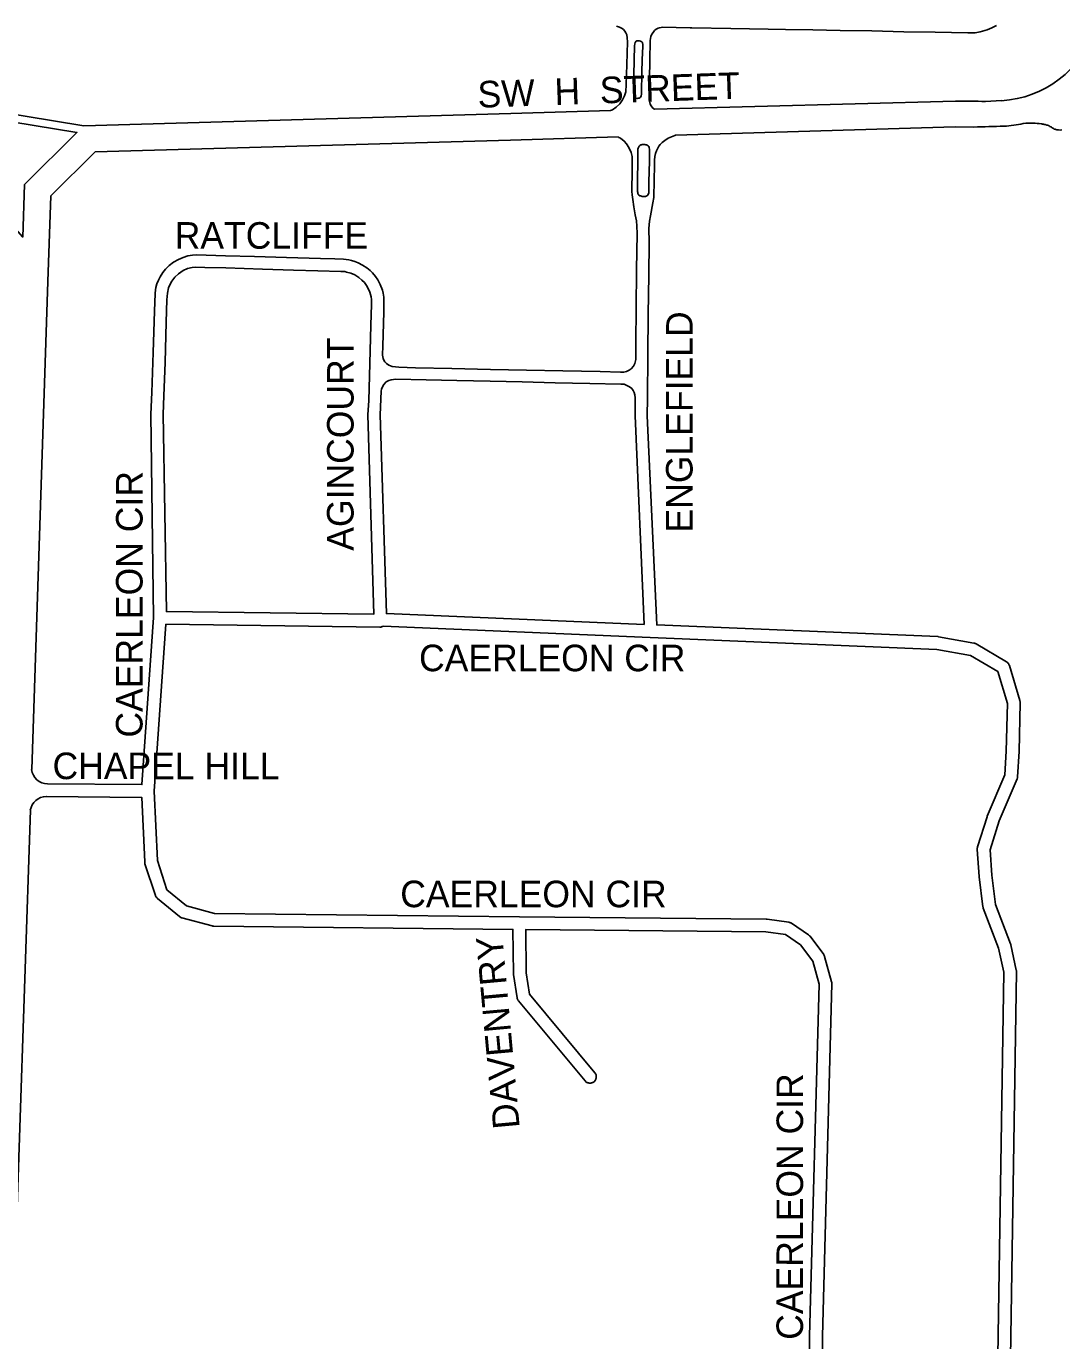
# Model space of a CAD drawing. Extents: x 0 to 712119, y 0 to 761125.
# Drawn here: x 656157 to 658107, y 728628 to 731101 of the extents above; entities that cross this region are included whole.
import ezdxf

# ---------------------------------------------------------------- set-up
doc = ezdxf.new("R2010")
doc.units = 0
doc.layers.add('PAVED ROADS', color=7, linetype='Continuous')
doc.layers.add('street names', color=7, linetype='Continuous')

msp = doc.modelspace()

# ---------------------------------------------------------------- linework, layer by layer
at = {"layer": 'PAVED ROADS'}
for points in [[(657267.9, 731101.4), (657274, 731099.7), (657278.9, 731097.1), (657281.3, 731095), (657283.8, 731092.2), (657286, 731088.9), (657287.5, 731085), (657288.5, 731079.4), (657288.9, 731071.9), (657287.5, 731029.4), (657286.7, 730992), (657285.5, 730977.9), (657283.5, 730970.5), (657279.6, 730963), (657274.2, 730955.5), (657267.3, 730949), (657260.5, 730944.3), (657257, 730942.5), (657069, 730937.3), (656265.2, 730914.2), (655883.9, 730976.8), (655357.5, 731004.3), (653623.9, 731094.8), (653552.8, 731124.8)], [(657906.8, 730960.6), (657339.5, 730945), (657336.8, 730947.1), (657333.4, 730951.4), (657331.4, 730954.7), (657330.1, 730960.6), (657329.6, 730967.3), (657331, 731036.7), (657331.5, 731074.7), (657332.8, 731082.2), (657334.8, 731086.2), (657337.2, 731089.7), (657339.9, 731093.3), (657343.1, 731096), (657346.5, 731097.8), (657348.9, 731098.6), (657355.2, 731099.4), (657380.8, 731099.1), (657407.1, 731098.3), (657410, 731098.5), (657410, 731098.5), (657483.4, 731097.4), (657553.8, 731096.1), (657586.5, 731095.3), (657637.7, 731094.3), (657689.3, 731093.4), (657748.8, 731092.4), (657809.1, 731090.9), (657868.1, 731090), (657929.7, 731089.1), (657943.3, 731089.2), (657952.7, 731090.7), (657966.1, 731094.3), (657974.9, 731098.2), (657984, 731102.9)], [(657992.9, 730961.3), (657963.3, 730959.8)], [(656167, 729702.5), (656197.4, 730620.7), (656202.8, 730781.9), (656286.3, 730864.8), (657068.4, 730887.2), (657271.5, 730893.1)], [(657271.5, 730893.1), (657272.7, 730892.2), (657275.6, 730890.6), (657282.7, 730885.2), (657287, 730880), (657291.7, 730873.1), (657295.8, 730863.9), (657297.4, 730856.1), (657297.9, 730852.8), (657297.8, 730830.9), (657297, 730790.5), (657297.5, 730783.9), (657298.8, 730775.3), (657300.7, 730761.4), (657303.3, 730746.4), (657305.7, 730734.9), (657306.3, 730725.2), (657306.8, 730711.2), (657305.7, 730643), (657305.3, 730570.3), (657304.8, 730506.1), (657304.3, 730474.4), (657303, 730466.5), (657300.3, 730461.4), (657296.1, 730456.9), (657292.3, 730454), (657287.3, 730451.8), (657282.3, 730450.5), (657276, 730450.2), (657237.2, 730451.5), (657167.2, 730453.1), (657098.8, 730454.3), (657030.8, 730455.5), (656957.9, 730457.4), (656890, 730458.6), (656858.3, 730459.8), (656846, 730461.1), (656839.6, 730463.6), (656835.3, 730466.5), (656832, 730470), (656829.7, 730473.9), (656829, 730475.9), (656828, 730479.2), (656827.7, 730482.5), (656828.1, 730500.1), (656830.2, 730563.1), (656830.4, 730581.2), (656829.9, 730591.3), (656828.7, 730599.3), (656827.5, 730604.5), (656823.5, 730615.2), (656818.7, 730624.2), (656814.7, 730630.6), (656808.5, 730637.5), (656804.6, 730641.4), (656797.8, 730647), (656789.8, 730652), (656782, 730656.2), (656775.7, 730658.7), (656769.2, 730660.6), (656764, 730661.9), (656753.9, 730663), (656737.7, 730663.4), (656711, 730664), (656646.8, 730665.9), (656586.3, 730667.8), (656531.7, 730669.3), (656495.6, 730670.7), (656477.9, 730671.2), (656469.6, 730670.5), (656461.1, 730669), (656452.2, 730666.4), (656443.2, 730662.7), (656433.9, 730657.4), (656425.8, 730650.9), (656419, 730643.9), (656413.9, 730637.7), (656408.8, 730629.6), (656405.8, 730623.6), (656402.9, 730616.9), (656400.8, 730609.4), (656400.3, 730605.2), (656399.3, 730598.2), (656398.1, 730565), (656395.9, 730487.4), (656393.3, 730412.4), (656391.5, 730371.3), (656396.6, 729988.8), (656374.6, 729674.2), (656196.9, 729675.7)], [(658010.3, 728595.5), (658021.2, 729322.4), (658021.2, 729323.4), (658021.2, 729324.3), (658021, 729325.3), (658010.8, 729372.7), (658010.5, 729373.7), (658010.3, 729374.4), (657981.7, 729448.5), (657974.9, 729503.5), (657971.5, 729551.6), (657989, 729605.8), (658022.5, 729684.8), (658022.7, 729685.7), (658023, 729686.6), (658023.2, 729687.8), (658023.4, 729688.8), (658026.1, 729736.3), (658026.1, 729736.8), (658028.2, 729828.4), (658028.2, 729829.4), (658028.2, 729830.3), (658027.9, 729831.2), (658027.6, 729832.2), (658007.9, 729898.2), (658007.7, 729899.2), (658007.2, 729900.1), (658006.7, 729901.3), (658006, 729902.2), (658005.2, 729902.9), (658004.5, 729903.8), (658003.6, 729904.5), (658002.6, 729905), (657945.3, 729939), (657944.3, 729939.7), (657943.4, 729939.9), (657942.4, 729940.3), (657941.3, 729940.5), (657874.7, 729952.5), (657874, 729952.8), (657873.1, 729952.7), (657344, 729974.7), (657326.2, 730368.3), (657326.5, 730401.4), (657327.2, 730483.1), (657327.9, 730559.2), (657328.8, 730633.1), (657329.4, 730695.2), (657329.3, 730721), (657330.6, 730734.4), (657332.2, 730744.4), (657336.9, 730769.2), (657338.6, 730779.1), (657339.3, 730811.6), (657339.9, 730839), (657339.7, 730849.4), (657340.5, 730856.4), (657341.7, 730862), (657343.3, 730866.6), (657345.8, 730871.6), (657348.2, 730875.9), (657350.4, 730878.5), (657354.4, 730882.4), (657358.9, 730886.4), (657365.6, 730890.5), (657371.6, 730893.5), (657378.1, 730896), (657379.5, 730896.5), (657905.7, 730912), (657941, 730911.5)], [(657986.2, 728597.8), (657997.3, 729321.5), (657987.7, 729366.6), (657958.8, 729441.4), (657958.6, 729442.4), (657958.3, 729443.3), (657958.1, 729444.2), (657951, 729500.9), (657951, 729501.4), (657947.3, 729552.1), (657947.3, 729553), (657947.3, 729553.9), (657947.5, 729554.9), (657947.7, 729555.8), (657947.9, 729556.8), (657966.2, 729613.8), (657966.4, 729614.7), (657999.6, 729692.3), (658002.2, 729737.4), (658004.3, 729827), (657986.3, 729886.8), (657934.9, 729917.4), (657871.3, 729928.7), (657331.6, 729951.2), (656829, 729972.3), (656827.9, 729971.8), (656827, 729971.5), (656826, 729971.1), (656824.9, 729970.8), (656823.9, 729970.8), (656822.7, 729970.8), (656419.7, 729975.9), (656397.7, 729662), (656403.7, 729531.3), (656421.8, 729476.4), (656458.6, 729446), (656511.5, 729431.8), (657085.4, 729425.6), (657550.2, 729421.3), (657550.9, 729421.3), (657551.6, 729421.1), (657592.6, 729415.1), (657593.8, 729414.9), (657594.8, 729414.7), (657595.9, 729414.3), (657596.9, 729413.8), (657597.8, 729413.4), (657629.8, 729391.7), (657630.5, 729391), (657631.2, 729390.3), (657631.9, 729389.6), (657632.7, 729389), (657658.3, 729354.5), (657658.8, 729353.6), (657659.3, 729352.6), (657659.8, 729351.5), (657660, 729350.5), (657673.2, 729303.1), (657673.5, 729302.2), (657673.7, 729301.3), (657673.8, 729300.3), (657673.8, 729299.6), (657655.8, 728636), (657656.4, 728584.3)], [(656194.6, 729651.7), (656374.2, 729650.2), (656379.8, 729528.6), (656379.8, 729527.5), (656380.1, 729526.5), (656380.3, 729525.4), (656399.9, 729465.6), (656400.2, 729464.7), (656400.7, 729463.8), (656401.1, 729463.1), (656401.6, 729462.1), (656402.4, 729461.5), (656403.1, 729460.8), (656403.8, 729460.1), (656445.4, 729425.7), (656446.1, 729425.3), (656447.1, 729424.6), (656448, 729424.1), (656449, 729423.7), (656449.9, 729423.5), (656506.9, 729408.2), (656507.8, 729408), (656508.7, 729407.8), (656509.7, 729407.8), (657073.2, 729401.8), (657074.3, 729318.7), (657074.3, 729317.7), (657074.3, 729316.8), (657081.1, 729272.8), (657081.4, 729271.8), (657081.6, 729270.7), (657082.1, 729269.7), (657082.6, 729268.8), (657083.1, 729267.9), (657083.8, 729267), (657208.9, 729116.6), (657209.6, 729116), (657210.6, 729115), (657211.3, 729114.3), (657212.3, 729113.9), (657213.2, 729113.4), (657214.4, 729113), (657215.3, 729112.8), (657216.5, 729112.6), (657217.7, 729112.4), (657218.6, 729112.4), (657219.8, 729112.4), (657221, 729112.7), (657221.9, 729112.9), (657223.1, 729113.4), (657224, 729113.9), (657224.9, 729114.4), (657225.9, 729115.1), (657226.6, 729115.8), (657227.5, 729116.8), (657228.2, 729117.5), (657228.6, 729118.5), (657229.1, 729119.4), (657229.5, 729120.6), (657229.7, 729121.6), (657229.9, 729122.7), (657230.1, 729123.9), (657230.1, 729124.8), (657230.1, 729126), (657229.8, 729127.2), (657229.6, 729128.1), (657229.1, 729129.3), (657228.6, 729130.2), (657228.1, 729131.1), (657227.4, 729132.1), (657104.4, 729279.8), (657098.2, 729319.7), (657097.4, 729401.4), (657549.1, 729397.3), (657586.5, 729392), (657614.4, 729372.8), (657637.6, 729341.8), (657649.8, 729298.4), (657631.8, 728636.2), (657631.9, 728635.7), (657632.5, 728581.9)], [(656132.9, 728673.9), (656164.5, 729626)]]:
    msp.add_lwpolyline(points, dxfattribs=at)
for points in [[(657316.7, 731038.3), (657317.6, 731063.9), (657317.6, 731067.2), (657317.1, 731070), (657316.4, 731071.3), (657314.8, 731072.8), (657313.2, 731073.4), (657310.9, 731073.9), (657308.4, 731074.2), (657306.3, 731073.8), (657305.1, 731073), (657303.4, 731070.8), (657302.8, 731068.1), (657302.2, 731064.6), (657300.9, 731010), (657300.8, 730972.4), (657301, 730970.3), (657301.6, 730968.4), (657302.1, 730967.6), (657303, 730966.8), (657304.8, 730965.9), (657306.8, 730965.6), (657309.3, 730965.7), (657311.1, 730966.3), (657312.7, 730967), (657313.5, 730967.8), (657314.4, 730969.8), (657315, 730973.9), (657316.2, 731016.6), (657316.7, 731036), (657316.7, 731038.5)], [(655930.3, 730954.3), (656252.3, 730901.5), (656153.4, 730803.4), (656150.2, 730704.6)], [(657308.5, 730852.6), (657307.8, 730806.7), (657307.7, 730792.7), (657307.9, 730790.3), (657308.2, 730788.5), (657308.5, 730786.9), (657309.2, 730785.4), (657309.5, 730784.5), (657310.3, 730783.4), (657311.7, 730782.5), (657313.1, 730781.9), (657315.2, 730781.3), (657316.5, 730781.2), (657319.5, 730780.9), (657321.2, 730780.9), (657322.9, 730781.1), (657324, 730781.7), (657325.5, 730782.5), (657326.9, 730783.7), (657327.9, 730785.3), (657328.8, 730787.5), (657328.8, 730808.8), (657330.1, 730847.5), (657330.3, 730869.5), (657329.7, 730873.4), (657328.8, 730874.9), (657327.7, 730876), (657326.1, 730877.3), (657324.9, 730878), (657323.5, 730878.4), (657321.8, 730878.6), (657320.1, 730878.9), (657318.6, 730878.8), (657316.7, 730878.7), (657315, 730878.4), (657313.9, 730877.9), (657312.2, 730876.8), (657310.8, 730875.8), (657310.2, 730874.7), (657309.4, 730873.3), (657308.9, 730871.8), (657308.4, 730870), (657308.5, 730854.2)], [(656414.5, 730371.2), (656420.8, 729999.9), (656811.2, 729994.9), (656800.2, 730370), (656801.7, 730397.1), (656803.8, 730466.9), (656805.9, 730539.1), (656807, 730577.5), (656806.8, 730587), (656806, 730592.4), (656803.7, 730601), (656800.6, 730607.7), (656797.3, 730613.3), (656793.4, 730618.8), (656788.8, 730623.8), (656783.2, 730628.3), (656775.7, 730633.4), (656767.9, 730636.5), (656759.6, 730638.8), (656756.4, 730639.5), (656749.2, 730639.8), (656706.1, 730641.2), (656659.9, 730642.6), (656601.8, 730644.5), (656532.9, 730646.8), (656493.1, 730647.4), (656475.3, 730648.1), (656469.2, 730647.2), (656460.5, 730645.3), (656452.1, 730641.5), (656443.2, 730635.7), (656436.5, 730628.9), (656430.6, 730621.6), (656426.9, 730614.6), (656424.7, 730608.8), (656422.7, 730599.2), (656421.7, 730586.6), (656420.1, 730544.5), (656418.4, 730468.3), (656416.1, 730405.6)], [(657303.2, 730368.4), (657303.5, 730399.2), (657303.3, 730402), (657302.6, 730407.5), (657301.3, 730412.2), (657299.8, 730415.7), (657296.8, 730419.4), (657292.9, 730422.8), (657287.9, 730425.4), (657282.7, 730427.6), (657276.5, 730427.9), (657217.7, 730429.2), (657152.5, 730430.5), (657090.4, 730431.9), (657030.6, 730433.4), (656967.7, 730434.6), (656910.1, 730435.9), (656853, 730437.4), (656843.6, 730436.2), (656839.4, 730435), (656834.6, 730432), (656830.2, 730427), (656827.7, 730423), (656825.9, 730418.1), (656825.2, 730414.5), (656823.4, 730369.9), (656835.1, 729996.2), (657320, 729975.6)]]:
    msp.add_lwpolyline(points, close=True, dxfattribs=at)
for centre, radius, start, end in [((657983, 731155.5), 194.5, 272.904, 342.3814), ((657852.3, 724769.8), 6191, 88.97331, 89.49637), ((657981.5, 731163.2), 250.5, 273.7233, 282.1379), ((658047.8, 730816.2), 103, 87.4571, 97.5876), ((658045.6, 730763.5), 155.7, 81.7448, 87.4947), ((658045.6, 730763.5), 155.7, 80.768, 81.7448), ((658061.7, 730859.9), 57.9, 74.8135, 81.2177), ((658066.2, 730876.3), 41, 65.8111, 74.8415), ((658338.5, 718204.8), 12713, 91.53564, 91.79183), ((658065, 730877.9), 40.1, 54.1756, 63.3335), ((658100.8, 730927.4), 21.1, 234.079, 251.3502), ((658104.2, 730941.6), 35.6, 253.3894, 263.5598), ((658103.2, 730932.4), 26.4, 263.4583, 277.1515), ((656197.3, 729706.2), 30.6, 187.0144, 269.1387), ((656194.5, 729621.3), 30.4, 89.7799, 171.1671)]:
    msp.add_arc(centre, radius, start, end, dxfattribs=at)

# ---------------------------------------------------------------- texts
at = {"layer": 'street names'}
for s, rotation, p in [('SW  H  STREET', 1.9838, (657007.5, 730947.9)), ('RATCLIFFE', 359.9838, (656436.3, 730682.7)), ('ENGLEFIELD', 89.9838, (657411.4, 730148.6)), ('AGINCOURT', 89.9838, (656773.1, 730114.3)), ('CAERLEON CIR', 89.9838, (656375.7, 729762.7)), ('CAERLEON CIR', 359.9838, (656896.4, 729887.6)), ('CHAPEL HILL', 359.9838, (656206.3, 729684.5)), ('CAERLEON CIR', 359.9838, (656861, 729443.5)), ('DAVENTRY', 95.182, (657086.1, 729028.4)), ('CAERLEON CIR', 89.9838, (657619.4, 728629.4))]:
    msp.add_text(s, height=50, rotation=rotation, dxfattribs=at).set_placement(p)

doc.saveas('drawing.dxf')
